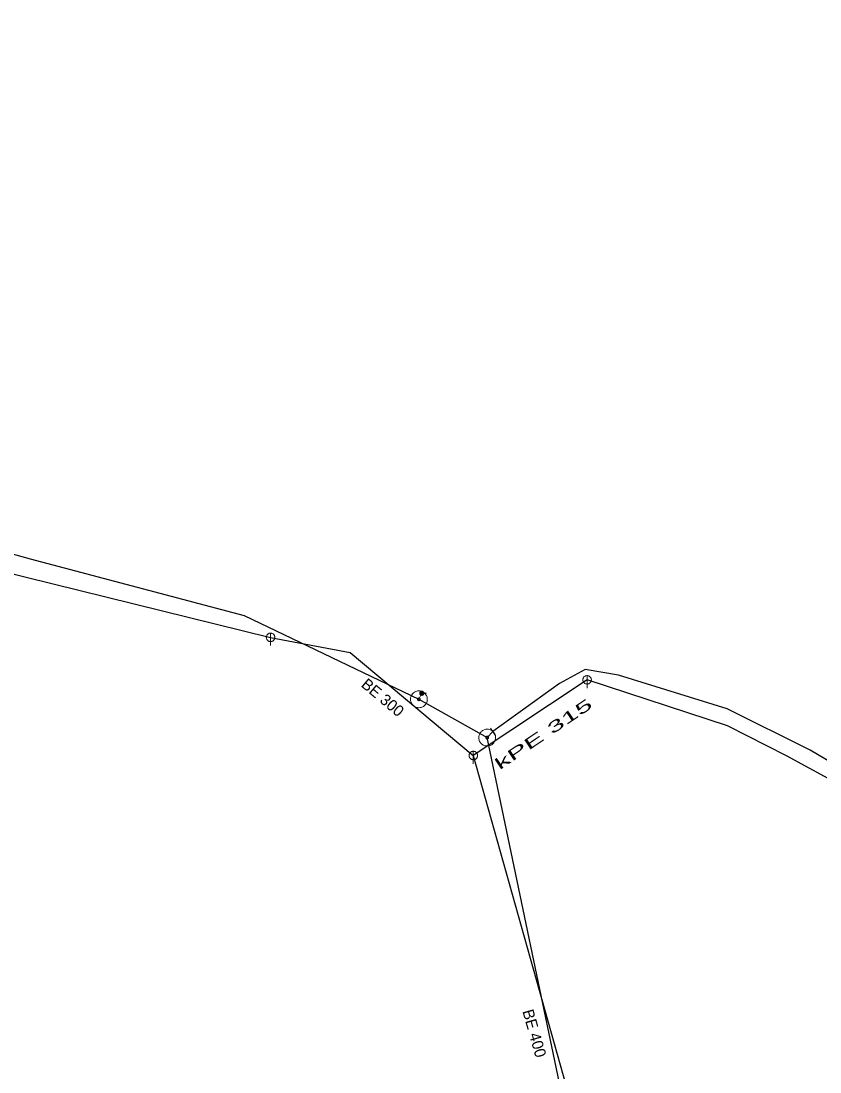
# Model space of a CAD drawing. Extents: x -687468 to -685917, y -974192 to -973456.
# Drawn here: x -686435.6 to -686388.2, y -973702 to -973639.5 of the extents above; entities that cross this region are included whole.
import ezdxf
from ezdxf.enums import TextEntityAlignment as Align

# ---------------------------------------------------------------- set-up
doc = ezdxf.new("R2010")
doc.units = 0
doc.header["$LTSCALE"] = 0.27
for name, color, linetype, lineweight in [('1', 7, 'Continuous', 13), ('14', 7, 'Continuous', 25), ('17', 7, 'Continuous', 25), ('22', 7, 'Continuous', 13), ('34', 7, 'Continuous', 13), ('47', 7, 'Continuous', 13), ('9', 7, 'Continuous', 13)]:
    doc.layers.add(name, color=color, linetype=linetype, lineweight=lineweight)

msp = doc.modelspace()

# ---------------------------------------------------------------- linework, layer by layer
at = {"layer": '14'}
msp.add_line((-686455.511, -973667.629), (-686420.804, -973676.186), dxfattribs=at)
at = {"layer": '14', "lineweight": 13}
for p, q in [((-686411.819, -973679.508), (-686411.992, -973679.868)), ((-686407.599, -973681.789), (-686407.937, -973682.144))]:
    msp.add_line(p, q, dxfattribs=at)
at = {"layer": '14'}
for points in [[(-686420.804, -973676.186), (-686416.08, -973677.091), (-686408.76, -973683.21)], [(-686402, -973678.71), (-686408.76, -973683.21), (-686398.605, -973719.354)], [(-686356.68, -973692.52), (-686362.98, -973692.39), (-686363.91, -973692.219), (-686372.649, -973690.57), (-686373.699, -973690.289), (-686383.199, -973687.01), (-686390.16, -973683.23), (-686393.66, -973681.449), (-686402, -973678.71)]]:
    msp.add_lwpolyline(points, dxfattribs=at)
at = {"layer": '17'}
msp.add_line((-686411.992, -973679.868), (-686407.937, -973682.144), dxfattribs=at)
for points in [[(-686518.85, -973620.049), (-686509.239, -973635.046), (-686491.169, -973646.693), (-686469.91, -973661.781), (-686435.092, -973671.522), (-686422.363, -973674.883), (-686411.992, -973679.868)], [(-686335.77, -973689.399), (-686343.64, -973690.559), (-686351.559, -973691.629), (-686356.76, -973691.77), (-686361.879, -973691.55), (-686364.14, -973691.41), (-686369.609, -973690.59), (-686377.059, -973688.55), (-686382.949, -973686.329), (-686388.76, -973682.89), (-686393.69, -973680.43), (-686400.129, -973678.44), (-686402.12, -973678.09), (-686403.64, -973678.93), (-686407.599, -973681.789)], [(-686390.37, -973750.001), (-686397.766, -973730.818), (-686407.937, -973682.144)]]:
    msp.add_lwpolyline(points, dxfattribs=at)
at = {"layer": '22'}
for p, q in [((-686420.803, -973675.934), (-686420.804, -973676.678)), ((-686401.999, -973678.458), (-686402, -973679.201)), ((-686408.759, -973682.958), (-686408.76, -973683.701))]:
    msp.add_line(p, q, dxfattribs=at)
for points in [[(-686420.552, -973676.186), (-686420.553, -973676.16), (-686420.557, -973676.134), (-686420.563, -973676.108), (-686420.573, -973676.084), (-686420.585, -973676.06), (-686420.599, -973676.038), (-686420.616, -973676.017), (-686420.634, -973675.999), (-686420.655, -973675.982), (-686420.677, -973675.968), (-686420.701, -973675.956), (-686420.725, -973675.946), (-686420.751, -973675.94), (-686420.777, -973675.936), (-686420.803, -973675.934), (-686420.829, -973675.935), (-686420.855, -973675.939), (-686420.881, -973675.945), (-686420.906, -973675.955), (-686420.929, -973675.967), (-686420.951, -973675.981), (-686420.972, -973675.998), (-686420.99, -973676.016), (-686421.007, -973676.037), (-686421.021, -973676.059), (-686421.033, -973676.083), (-686421.043, -973676.107), (-686421.05, -973676.133), (-686421.054, -973676.159), (-686421.056, -973676.185), (-686421.055, -973676.211), (-686421.051, -973676.237), (-686421.044, -973676.263), (-686421.034, -973676.288), (-686421.022, -973676.311), (-686421.008, -973676.333), (-686420.991, -973676.354), (-686420.973, -973676.372), (-686420.952, -973676.389), (-686420.93, -973676.403), (-686420.907, -973676.415), (-686420.882, -973676.425), (-686420.856, -973676.432), (-686420.83, -973676.436), (-686420.804, -973676.438), (-686420.778, -973676.437), (-686420.752, -973676.433), (-686420.726, -973676.426), (-686420.702, -973676.416), (-686420.678, -973676.404), (-686420.656, -973676.39), (-686420.635, -973676.373), (-686420.617, -973676.355), (-686420.6, -973676.334), (-686420.586, -973676.312), (-686420.574, -973676.289), (-686420.564, -973676.264), (-686420.558, -973676.238), (-686420.554, -973676.212)], [(-686401.748, -973678.71), (-686401.749, -973678.684), (-686401.753, -973678.658), (-686401.759, -973678.632), (-686401.769, -973678.608), (-686401.781, -973678.584), (-686401.795, -973678.562), (-686401.812, -973678.541), (-686401.83, -973678.523), (-686401.851, -973678.506), (-686401.873, -973678.492), (-686401.897, -973678.48), (-686401.921, -973678.47), (-686401.947, -973678.464), (-686401.973, -973678.46), (-686401.999, -973678.458), (-686402.025, -973678.459), (-686402.051, -973678.463), (-686402.077, -973678.469), (-686402.102, -973678.479), (-686402.125, -973678.491), (-686402.147, -973678.505), (-686402.168, -973678.522), (-686402.186, -973678.54), (-686402.203, -973678.561), (-686402.217, -973678.583), (-686402.229, -973678.607), (-686402.239, -973678.631), (-686402.246, -973678.657), (-686402.25, -973678.683), (-686402.252, -973678.709), (-686402.251, -973678.735), (-686402.247, -973678.761), (-686402.24, -973678.787), (-686402.23, -973678.812), (-686402.218, -973678.835), (-686402.204, -973678.857), (-686402.187, -973678.878), (-686402.169, -973678.896), (-686402.148, -973678.913), (-686402.126, -973678.927), (-686402.103, -973678.939), (-686402.078, -973678.949), (-686402.052, -973678.956), (-686402.026, -973678.96), (-686402, -973678.962), (-686401.974, -973678.961), (-686401.948, -973678.957), (-686401.922, -973678.95), (-686401.898, -973678.94), (-686401.874, -973678.928), (-686401.852, -973678.914), (-686401.831, -973678.897), (-686401.813, -973678.879), (-686401.796, -973678.858), (-686401.782, -973678.836), (-686401.77, -973678.813), (-686401.76, -973678.788), (-686401.754, -973678.762), (-686401.75, -973678.736)], [(-686408.508, -973683.21), (-686408.509, -973683.184), (-686408.513, -973683.158), (-686408.519, -973683.132), (-686408.529, -973683.108), (-686408.541, -973683.084), (-686408.555, -973683.062), (-686408.572, -973683.041), (-686408.59, -973683.023), (-686408.611, -973683.006), (-686408.633, -973682.992), (-686408.657, -973682.98), (-686408.681, -973682.97), (-686408.707, -973682.964), (-686408.733, -973682.96), (-686408.759, -973682.958), (-686408.785, -973682.959), (-686408.811, -973682.963), (-686408.837, -973682.969), (-686408.862, -973682.979), (-686408.885, -973682.991), (-686408.907, -973683.005), (-686408.928, -973683.022), (-686408.946, -973683.04), (-686408.963, -973683.061), (-686408.977, -973683.083), (-686408.989, -973683.107), (-686408.999, -973683.131), (-686409.006, -973683.157), (-686409.01, -973683.183), (-686409.012, -973683.209), (-686409.011, -973683.235), (-686409.007, -973683.261), (-686409, -973683.287), (-686408.99, -973683.312), (-686408.978, -973683.335), (-686408.964, -973683.357), (-686408.947, -973683.378), (-686408.929, -973683.396), (-686408.908, -973683.413), (-686408.886, -973683.427), (-686408.863, -973683.439), (-686408.838, -973683.449), (-686408.812, -973683.456), (-686408.786, -973683.46), (-686408.76, -973683.462), (-686408.734, -973683.461), (-686408.708, -973683.457), (-686408.682, -973683.45), (-686408.658, -973683.44), (-686408.634, -973683.428), (-686408.612, -973683.414), (-686408.591, -973683.397), (-686408.573, -973683.379), (-686408.556, -973683.358), (-686408.542, -973683.336), (-686408.53, -973683.313), (-686408.52, -973683.288), (-686408.514, -973683.262), (-686408.51, -973683.236)]]:
    msp.add_lwpolyline(points, close=True, dxfattribs=at)
at = {"layer": '34'}
msp.add_line((-686407.453, -973681.99), (-686407.744, -973681.587), dxfattribs=at)
at = {"layer": '47'}
for points in [[(-686411.492, -973679.843), (-686411.498, -973679.791), (-686411.508, -973679.739), (-686411.525, -973679.69), (-686411.545, -973679.642), (-686411.571, -973679.596), (-686411.603, -973679.554), (-686411.637, -973679.516), (-686411.676, -973679.48), (-686411.718, -973679.449), (-686411.763, -973679.423), (-686411.811, -973679.401), (-686411.861, -973679.385), (-686411.912, -973679.374), (-686411.964, -973679.369), (-686412.016, -973679.368), (-686412.068, -973679.374), (-686412.12, -973679.384), (-686412.17, -973679.401), (-686412.217, -973679.421), (-686412.263, -973679.447), (-686412.305, -973679.479), (-686412.344, -973679.514), (-686412.38, -973679.552), (-686412.411, -973679.594), (-686412.436, -973679.639), (-686412.458, -973679.687), (-686412.475, -973679.737), (-686412.485, -973679.788), (-686412.49, -973679.84), (-686412.491, -973679.892), (-686412.485, -973679.944), (-686412.475, -973679.996), (-686412.459, -973680.046), (-686412.438, -973680.093), (-686412.412, -973680.139), (-686412.381, -973680.181), (-686412.346, -973680.22), (-686412.308, -973680.256), (-686412.265, -973680.287), (-686412.22, -973680.312), (-686412.172, -973680.334), (-686412.123, -973680.351), (-686412.071, -973680.361), (-686412.019, -973680.366), (-686411.967, -973680.367), (-686411.915, -973680.361), (-686411.863, -973680.351), (-686411.814, -973680.335), (-686411.766, -973680.314), (-686411.72, -973680.288), (-686411.678, -973680.257), (-686411.64, -973680.223), (-686411.604, -973680.184), (-686411.573, -973680.141), (-686411.547, -973680.096), (-686411.525, -973680.048), (-686411.509, -973679.999), (-686411.498, -973679.947), (-686411.493, -973679.895)], [(-686411.91, -973679.863), (-686411.91, -973679.854), (-686411.912, -973679.847), (-686411.915, -973679.839), (-686411.918, -973679.831), (-686411.923, -973679.823), (-686411.928, -973679.816), (-686411.933, -973679.81), (-686411.94, -973679.804), (-686411.947, -973679.799), (-686411.954, -973679.795), (-686411.962, -973679.791), (-686411.97, -973679.788), (-686411.978, -973679.787), (-686411.987, -973679.785), (-686411.996, -973679.786), (-686412.005, -973679.786), (-686412.012, -973679.788), (-686412.02, -973679.791), (-686412.028, -973679.794), (-686412.036, -973679.799), (-686412.043, -973679.804), (-686412.049, -973679.809), (-686412.055, -973679.816), (-686412.061, -973679.823), (-686412.064, -973679.83), (-686412.068, -973679.838), (-686412.071, -973679.846), (-686412.072, -973679.854), (-686412.074, -973679.863), (-686412.073, -973679.872), (-686412.073, -973679.881), (-686412.071, -973679.888), (-686412.068, -973679.896), (-686412.065, -973679.904), (-686412.06, -973679.912), (-686412.056, -973679.919), (-686412.05, -973679.925), (-686412.043, -973679.931), (-686412.036, -973679.937), (-686412.029, -973679.94), (-686412.021, -973679.944), (-686412.013, -973679.947), (-686412.005, -973679.948), (-686411.996, -973679.95), (-686411.987, -973679.949), (-686411.978, -973679.949), (-686411.971, -973679.947), (-686411.963, -973679.944), (-686411.955, -973679.941), (-686411.947, -973679.936), (-686411.94, -973679.932), (-686411.934, -973679.926), (-686411.928, -973679.919), (-686411.923, -973679.912), (-686411.919, -973679.905), (-686411.915, -973679.897), (-686411.912, -973679.889), (-686411.911, -973679.881), (-686411.909, -973679.872)], [(-686407.586, -973682.5), (-686407.551, -973682.461), (-686407.519, -973682.419), (-686407.494, -973682.374), (-686407.471, -973682.327), (-686407.455, -973682.277), (-686407.444, -973682.225), (-686407.438, -973682.174), (-686407.438, -973682.121), (-686407.442, -973682.07), (-686407.452, -973682.018), (-686407.468, -973681.968), (-686407.49, -973681.92), (-686407.515, -973681.875), (-686407.546, -973681.832), (-686407.58, -973681.793), (-686407.619, -973681.758), (-686407.661, -973681.726), (-686407.707, -973681.7), (-686407.753, -973681.678), (-686407.803, -973681.662), (-686407.855, -973681.651), (-686407.907, -973681.645), (-686407.959, -973681.644), (-686408.011, -973681.649), (-686408.062, -973681.659), (-686408.112, -973681.675), (-686408.16, -973681.696), (-686408.205, -973681.722), (-686408.248, -973681.753), (-686408.287, -973681.787), (-686408.322, -973681.826), (-686408.354, -973681.868), (-686408.381, -973681.913), (-686408.402, -973681.96), (-686408.418, -973682.01), (-686408.43, -973682.061), (-686408.436, -973682.113), (-686408.437, -973682.166), (-686408.431, -973682.218), (-686408.421, -973682.269), (-686408.405, -973682.319), (-686408.385, -973682.367), (-686408.358, -973682.412), (-686408.327, -973682.455), (-686408.293, -973682.494), (-686408.254, -973682.529), (-686408.212, -973682.561), (-686408.168, -973682.587), (-686408.12, -973682.609), (-686408.07, -973682.625), (-686408.019, -973682.637), (-686407.968, -973682.642), (-686407.915, -973682.643), (-686407.863, -973682.638), (-686407.811, -973682.628), (-686407.761, -973682.612), (-686407.714, -973682.591), (-686407.668, -973682.565), (-686407.625, -973682.534)], [(-686407.879, -973682.202), (-686407.873, -973682.196), (-686407.868, -973682.189), (-686407.864, -973682.182), (-686407.86, -973682.174), (-686407.857, -973682.165), (-686407.856, -973682.157), (-686407.855, -973682.148), (-686407.854, -973682.14), (-686407.856, -973682.131), (-686407.857, -973682.123), (-686407.86, -973682.114), (-686407.863, -973682.107), (-686407.868, -973682.1), (-686407.872, -973682.092), (-686407.878, -973682.086), (-686407.884, -973682.08), (-686407.891, -973682.075), (-686407.898, -973682.071), (-686407.906, -973682.067), (-686407.915, -973682.064), (-686407.923, -973682.063), (-686407.932, -973682.062), (-686407.94, -973682.061), (-686407.949, -973682.062), (-686407.957, -973682.064), (-686407.966, -973682.067), (-686407.973, -973682.07), (-686407.98, -973682.075), (-686407.988, -973682.079), (-686407.994, -973682.085), (-686408, -973682.091), (-686408.005, -973682.098), (-686408.009, -973682.105), (-686408.013, -973682.113), (-686408.016, -973682.122), (-686408.018, -973682.129), (-686408.018, -973682.139), (-686408.019, -973682.147), (-686408.018, -973682.156), (-686408.016, -973682.164), (-686408.013, -973682.173), (-686408.01, -973682.18), (-686408.005, -973682.187), (-686408.001, -973682.195), (-686407.995, -973682.201), (-686407.989, -973682.207), (-686407.982, -973682.212), (-686407.975, -973682.216), (-686407.967, -973682.22), (-686407.958, -973682.223), (-686407.951, -973682.225), (-686407.941, -973682.225), (-686407.933, -973682.226), (-686407.924, -973682.224), (-686407.916, -973682.223), (-686407.907, -973682.22), (-686407.9, -973682.217), (-686407.893, -973682.212), (-686407.885, -973682.208)]]:
    msp.add_lwpolyline(points, close=True, dxfattribs=at)
at = {"layer": '9'}
msp.add_line((-686411.693, -973679.508), (-686411.567, -973679.508), dxfattribs=at)
for points in [[(-686411.819, -973679.634), (-686411.806, -973679.633), (-686411.793, -973679.631), (-686411.78, -973679.628), (-686411.768, -973679.623), (-686411.756, -973679.617), (-686411.745, -973679.61), (-686411.735, -973679.602), (-686411.725, -973679.592), (-686411.717, -973679.582), (-686411.71, -973679.571), (-686411.704, -973679.559), (-686411.699, -973679.547), (-686411.696, -973679.534), (-686411.694, -973679.521), (-686411.693, -973679.508), (-686411.693, -973679.495), (-686411.695, -973679.482), (-686411.698, -973679.469), (-686411.703, -973679.457), (-686411.709, -973679.445), (-686411.716, -973679.434), (-686411.724, -973679.424), (-686411.734, -973679.414), (-686411.744, -973679.406), (-686411.755, -973679.399), (-686411.767, -973679.393), (-686411.779, -973679.388), (-686411.792, -973679.385), (-686411.805, -973679.383), (-686411.818, -973679.382), (-686411.831, -973679.382), (-686411.844, -973679.384), (-686411.857, -973679.387), (-686411.869, -973679.392), (-686411.881, -973679.398), (-686411.892, -973679.405), (-686411.902, -973679.413), (-686411.912, -973679.423), (-686411.92, -973679.433), (-686411.927, -973679.444), (-686411.933, -973679.456), (-686411.938, -973679.468), (-686411.941, -973679.481), (-686411.943, -973679.494), (-686411.945, -973679.507), (-686411.944, -973679.52), (-686411.942, -973679.533), (-686411.939, -973679.546), (-686411.934, -973679.558), (-686411.928, -973679.57), (-686411.921, -973679.581), (-686411.913, -973679.591), (-686411.903, -973679.601), (-686411.893, -973679.609), (-686411.882, -973679.616), (-686411.87, -973679.622), (-686411.858, -973679.627), (-686411.845, -973679.63), (-686411.832, -973679.632)], [(-686411.819, -973679.614), (-686411.808, -973679.614), (-686411.797, -973679.612), (-686411.786, -973679.609), (-686411.776, -973679.605), (-686411.766, -973679.6), (-686411.757, -973679.594), (-686411.748, -973679.587), (-686411.74, -973679.579), (-686411.733, -973679.57), (-686411.727, -973679.561), (-686411.722, -973679.551), (-686411.718, -973679.541), (-686411.715, -973679.53), (-686411.713, -973679.519), (-686411.713, -973679.508), (-686411.712, -973679.497), (-686411.714, -973679.486), (-686411.717, -973679.475), (-686411.721, -973679.465), (-686411.726, -973679.455), (-686411.732, -973679.446), (-686411.739, -973679.437), (-686411.747, -973679.429), (-686411.756, -973679.422), (-686411.765, -973679.416), (-686411.775, -973679.411), (-686411.785, -973679.407), (-686411.796, -973679.404), (-686411.807, -973679.402), (-686411.818, -973679.402), (-686411.829, -973679.401), (-686411.84, -973679.403), (-686411.851, -973679.406), (-686411.861, -973679.41), (-686411.871, -973679.415), (-686411.88, -973679.421), (-686411.889, -973679.428), (-686411.897, -973679.436), (-686411.904, -973679.445), (-686411.91, -973679.454), (-686411.915, -973679.464), (-686411.919, -973679.474), (-686411.922, -973679.485), (-686411.924, -973679.496), (-686411.925, -973679.507), (-686411.925, -973679.518), (-686411.923, -973679.529), (-686411.92, -973679.54), (-686411.916, -973679.55), (-686411.911, -973679.56), (-686411.905, -973679.569), (-686411.898, -973679.578), (-686411.89, -973679.586), (-686411.881, -973679.593), (-686411.872, -973679.599), (-686411.862, -973679.604), (-686411.852, -973679.608), (-686411.841, -973679.611), (-686411.83, -973679.613)], [(-686411.819, -973679.595), (-686411.81, -973679.594), (-686411.801, -973679.593), (-686411.792, -973679.59), (-686411.784, -973679.587), (-686411.776, -973679.583), (-686411.768, -973679.578), (-686411.761, -973679.572), (-686411.755, -973679.566), (-686411.749, -973679.559), (-686411.744, -973679.551), (-686411.74, -973679.543), (-686411.737, -973679.535), (-686411.734, -973679.526), (-686411.733, -973679.517), (-686411.732, -973679.508), (-686411.732, -973679.499), (-686411.733, -973679.49), (-686411.736, -973679.481), (-686411.739, -973679.473), (-686411.743, -973679.465), (-686411.748, -973679.457), (-686411.754, -973679.45), (-686411.76, -973679.444), (-686411.767, -973679.438), (-686411.775, -973679.433), (-686411.783, -973679.429), (-686411.791, -973679.426), (-686411.8, -973679.423), (-686411.809, -973679.422), (-686411.818, -973679.421), (-686411.827, -973679.421), (-686411.836, -973679.422), (-686411.845, -973679.425), (-686411.853, -973679.428), (-686411.861, -973679.432), (-686411.869, -973679.437), (-686411.876, -973679.443), (-686411.882, -973679.449), (-686411.888, -973679.456), (-686411.893, -973679.464), (-686411.897, -973679.472), (-686411.9, -973679.48), (-686411.903, -973679.489), (-686411.904, -973679.498), (-686411.906, -973679.507), (-686411.905, -973679.516), (-686411.904, -973679.525), (-686411.901, -973679.534), (-686411.898, -973679.542), (-686411.894, -973679.55), (-686411.889, -973679.558), (-686411.883, -973679.565), (-686411.877, -973679.571), (-686411.87, -973679.577), (-686411.862, -973679.582), (-686411.854, -973679.586), (-686411.846, -973679.589), (-686411.837, -973679.592), (-686411.828, -973679.593)], [(-686411.819, -973679.575), (-686411.812, -973679.575), (-686411.805, -973679.573), (-686411.798, -973679.572), (-686411.792, -973679.569), (-686411.786, -973679.566), (-686411.78, -973679.562), (-686411.774, -973679.558), (-686411.769, -973679.553), (-686411.765, -973679.547), (-686411.761, -973679.541), (-686411.758, -973679.535), (-686411.755, -973679.529), (-686411.754, -973679.522), (-686411.752, -973679.515), (-686411.752, -973679.508), (-686411.751, -973679.501), (-686411.753, -973679.494), (-686411.754, -973679.487), (-686411.757, -973679.481), (-686411.76, -973679.474), (-686411.764, -973679.469), (-686411.768, -973679.463), (-686411.773, -973679.458), (-686411.779, -973679.454), (-686411.785, -973679.45), (-686411.791, -973679.447), (-686411.797, -973679.444), (-686411.804, -973679.442), (-686411.811, -973679.441), (-686411.818, -973679.441), (-686411.825, -973679.44), (-686411.832, -973679.441), (-686411.839, -973679.443), (-686411.845, -973679.446), (-686411.852, -973679.449), (-686411.857, -973679.453), (-686411.863, -973679.457), (-686411.868, -973679.462), (-686411.872, -973679.468), (-686411.876, -973679.473), (-686411.879, -973679.48), (-686411.882, -973679.486), (-686411.884, -973679.493), (-686411.885, -973679.5), (-686411.886, -973679.507), (-686411.886, -973679.514), (-686411.885, -973679.521), (-686411.883, -973679.528), (-686411.88, -973679.534), (-686411.877, -973679.54), (-686411.873, -973679.546), (-686411.869, -973679.552), (-686411.864, -973679.557), (-686411.858, -973679.561), (-686411.853, -973679.565), (-686411.846, -973679.568), (-686411.84, -973679.571), (-686411.833, -973679.572), (-686411.826, -973679.574)], [(-686411.819, -973679.555), (-686411.814, -973679.555), (-686411.809, -973679.554), (-686411.804, -973679.553), (-686411.8, -973679.551), (-686411.795, -973679.549), (-686411.791, -973679.546), (-686411.788, -973679.543), (-686411.784, -973679.539), (-686411.781, -973679.536), (-686411.778, -973679.532), (-686411.776, -973679.527), (-686411.774, -973679.523), (-686411.773, -973679.518), (-686411.772, -973679.513), (-686411.772, -973679.508), (-686411.771, -973679.503), (-686411.772, -973679.498), (-686411.773, -973679.493), (-686411.775, -973679.489), (-686411.777, -973679.484), (-686411.78, -973679.48), (-686411.783, -973679.476), (-686411.787, -973679.473), (-686411.79, -973679.47), (-686411.794, -973679.467), (-686411.799, -973679.465), (-686411.803, -973679.463), (-686411.808, -973679.462), (-686411.813, -973679.461), (-686411.818, -973679.461), (-686411.823, -973679.46), (-686411.828, -973679.461), (-686411.833, -973679.462), (-686411.837, -973679.464), (-686411.842, -973679.466), (-686411.846, -973679.469), (-686411.85, -973679.472), (-686411.853, -973679.475), (-686411.856, -973679.479), (-686411.859, -973679.483), (-686411.861, -973679.488), (-686411.863, -973679.492), (-686411.864, -973679.497), (-686411.865, -973679.502), (-686411.866, -973679.507), (-686411.866, -973679.512), (-686411.865, -973679.517), (-686411.864, -973679.522), (-686411.862, -973679.526), (-686411.86, -973679.531), (-686411.857, -973679.535), (-686411.854, -973679.538), (-686411.851, -973679.542), (-686411.847, -973679.545), (-686411.843, -973679.548), (-686411.838, -973679.55), (-686411.834, -973679.552), (-686411.829, -973679.553), (-686411.824, -973679.554)], [(-686411.819, -973679.535), (-686411.816, -973679.535), (-686411.813, -973679.535), (-686411.811, -973679.534), (-686411.808, -973679.533), (-686411.805, -973679.532), (-686411.803, -973679.53), (-686411.801, -973679.528), (-686411.799, -973679.526), (-686411.797, -973679.524), (-686411.795, -973679.522), (-686411.794, -973679.519), (-686411.793, -973679.516), (-686411.792, -973679.514), (-686411.792, -973679.511), (-686411.792, -973679.508), (-686411.791, -973679.505), (-686411.791, -973679.502), (-686411.792, -973679.499), (-686411.793, -973679.497), (-686411.794, -973679.494), (-686411.796, -973679.492), (-686411.798, -973679.489), (-686411.8, -973679.487), (-686411.802, -973679.486), (-686411.804, -973679.484), (-686411.807, -973679.483), (-686411.81, -973679.482), (-686411.812, -973679.481), (-686411.815, -973679.481), (-686411.818, -973679.48), (-686411.821, -973679.48), (-686411.824, -973679.48), (-686411.827, -973679.481), (-686411.829, -973679.482), (-686411.832, -973679.483), (-686411.834, -973679.485), (-686411.837, -973679.486), (-686411.839, -973679.488), (-686411.84, -973679.491), (-686411.842, -973679.493), (-686411.843, -973679.496), (-686411.844, -973679.498), (-686411.845, -973679.501), (-686411.845, -973679.504), (-686411.847, -973679.507), (-686411.846, -973679.51), (-686411.846, -973679.513), (-686411.845, -973679.515), (-686411.844, -973679.518), (-686411.843, -973679.521), (-686411.841, -973679.523), (-686411.84, -973679.525), (-686411.838, -973679.527), (-686411.835, -973679.529), (-686411.833, -973679.531), (-686411.83, -973679.532), (-686411.828, -973679.533), (-686411.825, -973679.534), (-686411.822, -973679.534)], [(-686411.819, -973679.516), (-686411.818, -973679.516), (-686411.817, -973679.516), (-686411.817, -973679.515), (-686411.816, -973679.515), (-686411.815, -973679.515), (-686411.814, -973679.514), (-686411.814, -973679.514), (-686411.813, -973679.513), (-686411.813, -973679.513), (-686411.812, -973679.512), (-686411.812, -973679.511), (-686411.812, -973679.51), (-686411.811, -973679.51), (-686411.811, -973679.509), (-686411.811, -973679.508), (-686411.811, -973679.507), (-686411.811, -973679.506), (-686411.811, -973679.506), (-686411.811, -973679.505), (-686411.811, -973679.504), (-686411.812, -973679.503), (-686411.812, -973679.503), (-686411.813, -973679.502), (-686411.813, -973679.502), (-686411.814, -973679.501), (-686411.815, -973679.501), (-686411.816, -973679.5), (-686411.816, -973679.5), (-686411.817, -973679.5), (-686411.818, -973679.5), (-686411.819, -973679.5), (-686411.82, -973679.5), (-686411.82, -973679.5), (-686411.821, -973679.5), (-686411.822, -973679.5), (-686411.823, -973679.501), (-686411.823, -973679.501), (-686411.824, -973679.502), (-686411.824, -973679.502), (-686411.825, -973679.503), (-686411.825, -973679.504), (-686411.826, -973679.505), (-686411.826, -973679.505), (-686411.826, -973679.506), (-686411.827, -973679.507), (-686411.827, -973679.508), (-686411.827, -973679.509), (-686411.827, -973679.509), (-686411.826, -973679.51), (-686411.826, -973679.511), (-686411.825, -973679.512), (-686411.825, -973679.512), (-686411.824, -973679.513), (-686411.824, -973679.513), (-686411.823, -973679.514), (-686411.822, -973679.514), (-686411.821, -973679.514), (-686411.821, -973679.516), (-686411.82, -973679.516)]]:
    msp.add_lwpolyline(points, close=True, dxfattribs=at)
msp.add_lwpolyline([(-686411.601, -973679.477), (-686411.567, -973679.508), (-686411.602, -973679.539)], dxfattribs=at)

# ---------------------------------------------------------------- texts
at = {"layer": '1'}
for s, rotation, p in [('BE 300', 320, (-686414.353, -973680.015)), ('BE 400', 286, (-686405.449, -973699.816))]:
    msp.add_text(s, height=0.6667, rotation=rotation, dxfattribs=at).set_placement(p, align=Align.CENTER)
at = {"layer": '1', "width": 2}
msp.add_text('kPE 315 ', height=0.6667, rotation=34, dxfattribs=at).set_placement((-686404.205, -973682.066), align=Align.CENTER)

doc.saveas('drawing.dxf')
